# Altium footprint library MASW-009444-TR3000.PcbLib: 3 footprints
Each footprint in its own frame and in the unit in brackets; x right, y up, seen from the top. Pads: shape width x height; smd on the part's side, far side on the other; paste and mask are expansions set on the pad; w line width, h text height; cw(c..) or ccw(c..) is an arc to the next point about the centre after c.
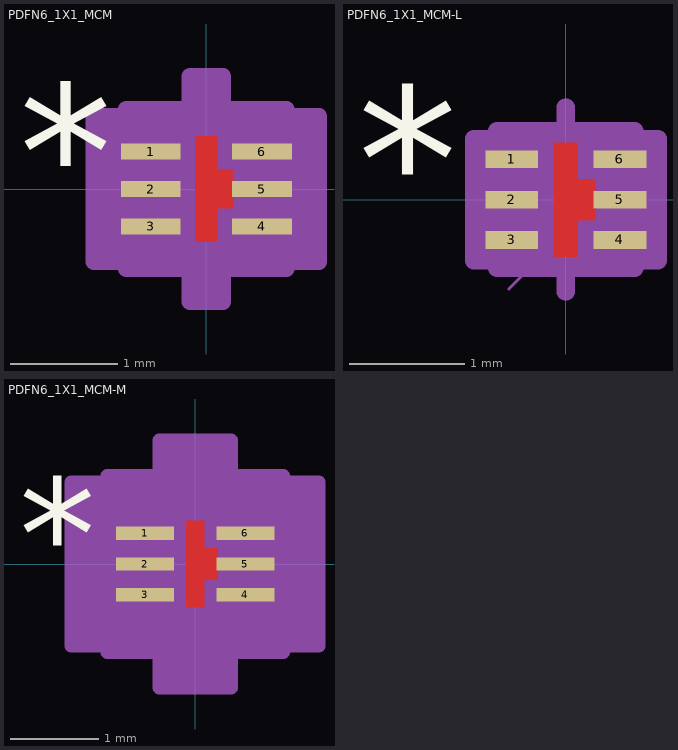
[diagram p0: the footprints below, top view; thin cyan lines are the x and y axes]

## PDFN6_1X1_MCM [mil]
pads (6):
  rect 22x6 smd paste+0 mask+0: 1(-20.5,13.78) 2(-20.5,0) 3(-20.5,-13.78) 4(20.5,-13.78) 5(20.5,0) 6(20.5,13.78)
Top Layer:
  region: -4,-19.5 -4,19.5 4,19.5 4,-19.5
  region: 2,-7 2,7 10,7 10,-7
Top Overlay:
  text "*" at -69,-11.22 h50
Top Paste:
  region: -4,-19.5 -4,19.5 4,19.5 4,-19.5
  region: 2,-7 2,7 10,7 10,-7
Top Solder:
  region: -4,-19.5 -4,19.5 4,19.5 4,-19.5
  region: 2,-7 2,7 10,7 10,-7
Mechanical 13:
  lines w1: -19.5,-30.5 30.5,19.5 ; -19.5,-17.78 -19.5,-9.78 ; -19.5,-17.78 -19.5,-9.78 ; -19.5,-17.78 -19.5,-17.78 ; -19.5,-9.78 -19.5,-9.78 ; -19.5,-4 -19.5,4 ; -19.5,-4 -19.5,4 ; -19.5,-4 -19.5,-4 ; -19.5,4 -19.5,4 ; -19.5,9.78 -19.5,17.78 ; -19.5,9.78 -19.5,17.78 ; -19.5,9.78 -19.5,9.78 ; -19.5,17.78 -19.5,17.78 ; 19.5,-17.78 19.5,-9.78 ; 19.5,-17.78 19.5,-17.78 ; 19.5,-17.78 19.5,-9.78 ; 19.5,-9.78 19.5,-9.78 ; 19.5,-4 19.5,4 ; 19.5,-4 19.5,-4 ; 19.5,-4 19.5,4 ; 19.5,4 19.5,4 ; 19.5,9.78 19.5,17.78 ; 19.5,9.78 19.5,9.78 ; 19.5,9.78 19.5,17.78 ; 19.5,17.78 19.5,17.78 ; -19.5,-19.5 19.5,-19.5 19.5,19.5 -19.5,19.5 -19.5,-19.5
  text "*" at 3,-11.22 h50
Mechanical 15:
  region: -6.11,-29.5 -29.5,-29.5 -29.5,-26.78 -41.5,-26.78 -41.5,26.78 -29.5,26.78 -29.5,29.5 -6.11,29.5 -6.11,41.5 6.11,41.5 6.11,29.5 29.5,29.5 29.5,26.78 41.5,26.78 41.5,-26.78 29.5,-26.78 29.5,-29.5 6.11,-29.5 6.11,-41.5 -6.11,-41.5
  lines w6: -41.5,-26.78 -29.5,-26.78 -29.5,-29.5 -6.11,-29.5 -6.11,-41.5 6.11,-41.5 6.11,-29.5 29.5,-29.5 29.5,-26.78 41.5,-26.78 41.5,26.78 29.5,26.78 29.5,29.5 6.11,29.5 6.11,41.5 -6.11,41.5 -6.11,29.5 -29.5,29.5 -29.5,26.78 -41.5,26.78 -41.5,-26.78
3D body "PDFN6_1X1_MCM.step": height 20.12, standoff 0, extent -19.49,-19.49 19.49,19.49

## PDFN6_1X1_MCM-L [mil]
pads (6):
  rect 18x6 smd paste+0 mask+0: 1(-18.5,13.78) 2(-18.5,0) 3(-18.5,-13.78) 4(18.5,-13.78) 5(18.5,0) 6(18.5,13.78)
Top Layer:
  region: -4,-19.5 -4,19.5 4,19.5 4,-19.5
  region: 2,-7 2,7 10,7 10,-7
Top Overlay:
  text "*" at -71,-11.22 h50
Top Paste:
  region: -4,-19.5 -4,19.5 4,19.5 4,-19.5
  region: 2,-7 2,7 10,7 10,-7
Top Solder:
  region: -4,-19.5 -4,19.5 4,19.5 4,-19.5
  region: 2,-7 2,7 10,7 10,-7
Mechanical 13:
  lines w1: -19.5,-30.5 30.5,19.5 ; -19.5,-17.78 -19.5,-9.78 ; -19.5,-17.78 -19.5,-9.78 ; -19.5,-17.78 -19.5,-17.78 ; -19.5,-9.78 -19.5,-9.78 ; -19.5,-4 -19.5,4 ; -19.5,-4 -19.5,4 ; -19.5,-4 -19.5,-4 ; -19.5,4 -19.5,4 ; -19.5,9.78 -19.5,17.78 ; -19.5,9.78 -19.5,17.78 ; -19.5,9.78 -19.5,9.78 ; -19.5,17.78 -19.5,17.78 ; 19.5,-17.78 19.5,-9.78 ; 19.5,-17.78 19.5,-17.78 ; 19.5,-17.78 19.5,-9.78 ; 19.5,-9.78 19.5,-9.78 ; 19.5,-4 19.5,4 ; 19.5,-4 19.5,-4 ; 19.5,-4 19.5,4 ; 19.5,4 19.5,4 ; 19.5,9.78 19.5,17.78 ; 19.5,9.78 19.5,9.78 ; 19.5,9.78 19.5,17.78 ; 19.5,17.78 19.5,17.78 ; -19.5,-19.5 19.5,-19.5 19.5,19.5 -19.5,19.5 -19.5,-19.5
  text "*" at 9,-11.22 h50
Mechanical 15:
  region: -0.11,-23.5 -23.5,-23.5 -23.5,-20.78 -31.5,-20.78 -31.5,20.78 -23.5,20.78 -23.5,23.5 -0.11,23.5 -0.11,31.5 0.11,31.5 0.11,23.5 23.5,23.5 23.5,20.78 31.5,20.78 31.5,-20.78 23.5,-20.78 23.5,-23.5 0.11,-23.5 0.11,-31.5 -0.11,-31.5
  lines w6: -31.5,-20.78 -23.5,-20.78 -23.5,-23.5 -0.11,-23.5 -0.11,-31.5 0.11,-31.5 0.11,-23.5 23.5,-23.5 23.5,-20.78 31.5,-20.78 31.5,20.78 23.5,20.78 23.5,23.5 0.11,23.5 0.11,31.5 -0.11,31.5 -0.11,23.5 -23.5,23.5 -23.5,20.78 -31.5,20.78 -31.5,-20.78
3D body "PDFN6_1X1_MCM.step": height 20.12, standoff 0, extent -19.49,-19.49 19.49,19.49

## PDFN6_1X1_MCM-M [mil]
pads (6):
  rect 26x6 smd paste+0 mask+0: 1(-22.5,13.78) 2(-22.5,0) 3(-22.5,-13.78) 4(22.5,-13.78) 5(22.5,0) 6(22.5,13.78)
Top Layer:
  region: -4,-19.5 -4,19.5 4,19.5 4,-19.5
  region: 2,-7 2,7 10,7 10,-7
Top Overlay:
  text "*" at -79,-11.22 h50
Top Paste:
  region: -4,-19.5 -4,19.5 4,19.5 4,-19.5
  region: 2,-7 2,7 10,7 10,-7
Top Solder:
  region: -4,-19.5 -4,19.5 4,19.5 4,-19.5
  region: 2,-7 2,7 10,7 10,-7
Mechanical 13:
  lines w1: -19.5,-30.5 30.5,19.5 ; -19.5,-17.78 -19.5,-9.78 ; -19.5,-17.78 -19.5,-9.78 ; -19.5,-17.78 -19.5,-17.78 ; -19.5,-9.78 -19.5,-9.78 ; -19.5,-4 -19.5,4 ; -19.5,-4 -19.5,4 ; -19.5,-4 -19.5,-4 ; -19.5,4 -19.5,4 ; -19.5,9.78 -19.5,17.78 ; -19.5,9.78 -19.5,17.78 ; -19.5,9.78 -19.5,9.78 ; -19.5,17.78 -19.5,17.78 ; 19.5,-17.78 19.5,-9.78 ; 19.5,-17.78 19.5,-17.78 ; 19.5,-17.78 19.5,-9.78 ; 19.5,-9.78 19.5,-9.78 ; 19.5,-4 19.5,4 ; 19.5,-4 19.5,-4 ; 19.5,-4 19.5,4 ; 19.5,4 19.5,4 ; 19.5,9.78 19.5,17.78 ; 19.5,9.78 19.5,9.78 ; 19.5,9.78 19.5,17.78 ; 19.5,17.78 19.5,17.78 ; -19.5,-19.5 19.5,-19.5 19.5,19.5 -19.5,19.5 -19.5,-19.5
  text "*" at 9,-11.22 h50
Mechanical 15:
  region: -16.11,-39.5 -39.5,-39.5 -39.5,-36.78 -55.5,-36.78 -55.5,36.78 -39.5,36.78 -39.5,39.5 -16.11,39.5 -16.11,55.5 16.11,55.5 16.11,39.5 39.5,39.5 39.5,36.78 55.5,36.78 55.5,-36.78 39.5,-36.78 39.5,-39.5 16.11,-39.5 16.11,-55.5 -16.11,-55.5
  lines w6: -55.5,-36.78 -39.5,-36.78 -39.5,-39.5 -16.11,-39.5 -16.11,-55.5 16.11,-55.5 16.11,-39.5 39.5,-39.5 39.5,-36.78 55.5,-36.78 55.5,36.78 39.5,36.78 39.5,39.5 16.11,39.5 16.11,55.5 -16.11,55.5 -16.11,39.5 -39.5,39.5 -39.5,36.78 -55.5,36.78 -55.5,-36.78
3D body "PDFN6_1X1_MCM.step": height 20.12, standoff 0, extent -19.49,-19.49 19.49,19.49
